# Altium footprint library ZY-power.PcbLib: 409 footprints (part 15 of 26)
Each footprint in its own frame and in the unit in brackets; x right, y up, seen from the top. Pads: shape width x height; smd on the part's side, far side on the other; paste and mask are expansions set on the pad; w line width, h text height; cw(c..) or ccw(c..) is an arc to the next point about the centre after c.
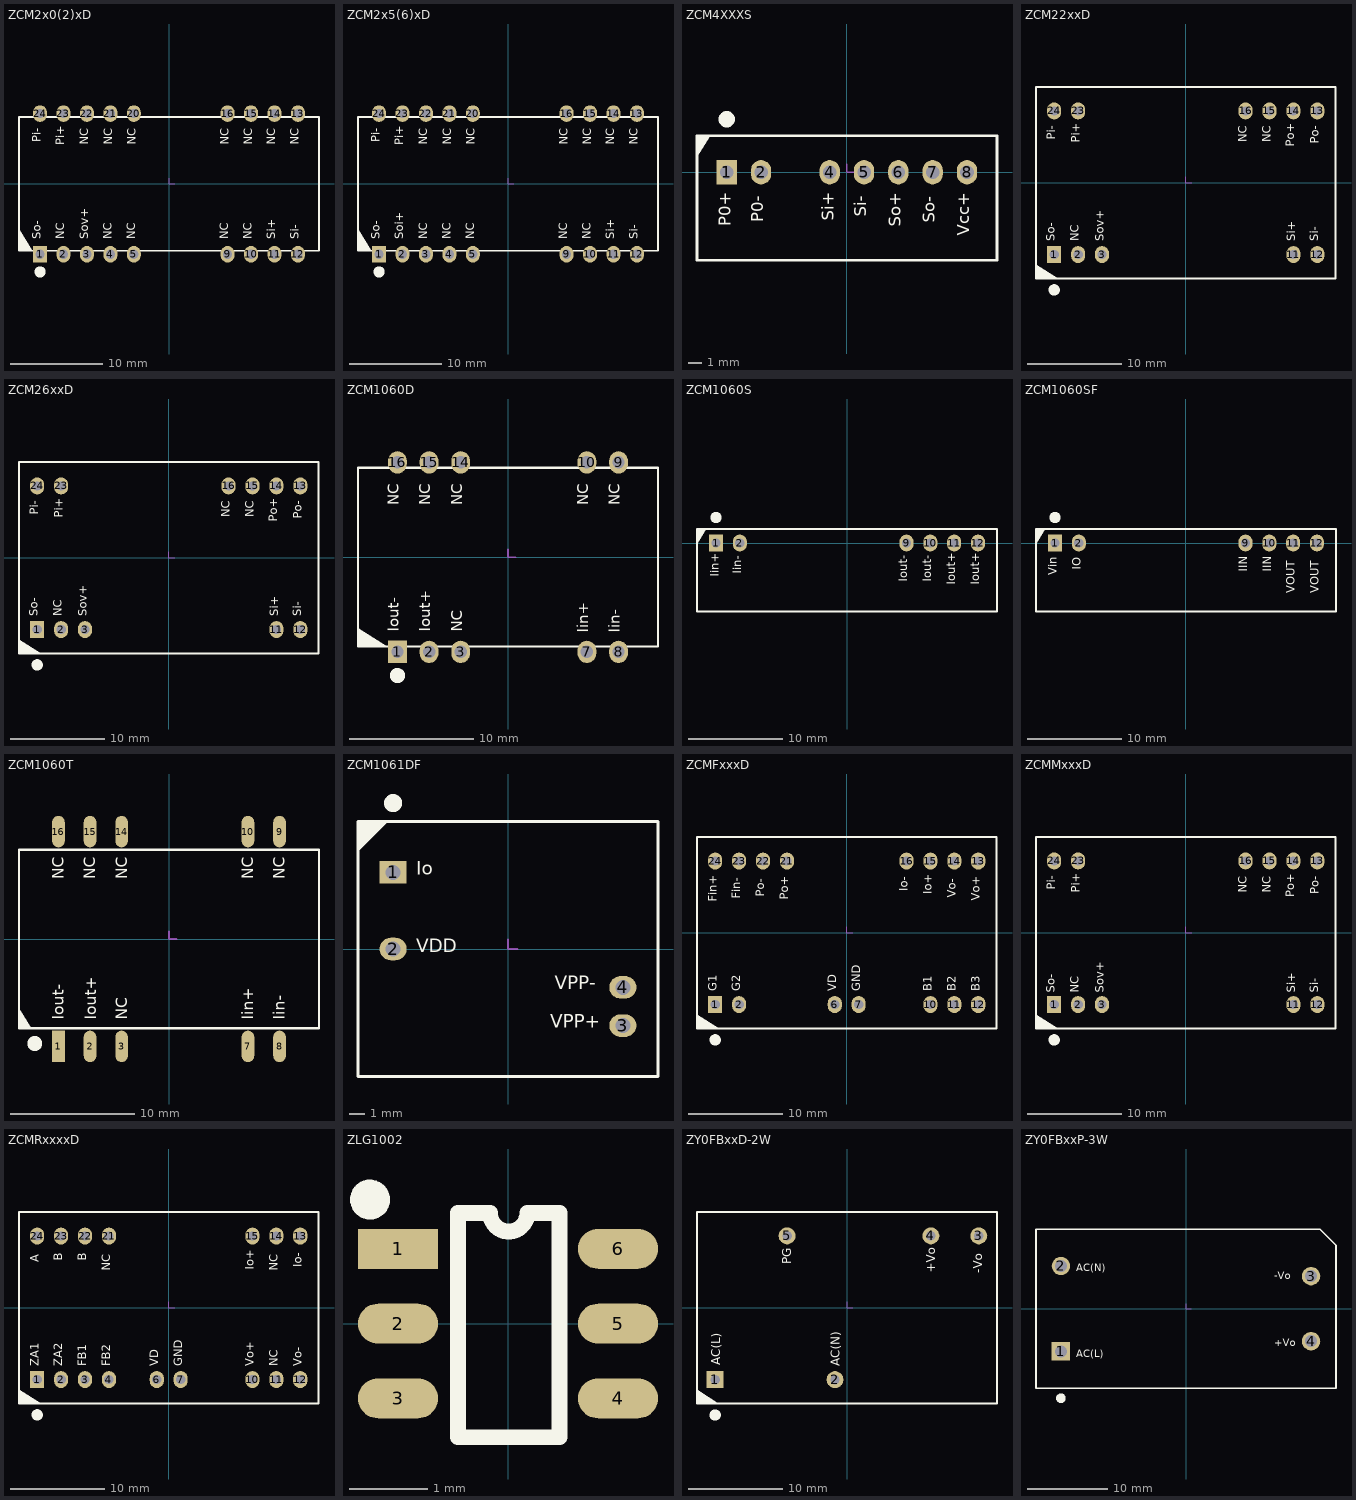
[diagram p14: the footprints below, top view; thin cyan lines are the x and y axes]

## ZCM2x0(2)xD [mm]
height 8.5
pads (18):
  rect 1.5x1.8 hole 1: 1(-13.97,-7.62)
  oval 1.5x1.8 hole 1: 2(-11.43,-7.62) 3(-8.89,-7.62) 4(-6.35,-7.62) 5(-3.81,-7.62) 9(6.35,-7.62) 10(8.89,-7.62) 11(11.43,-7.62) 12(13.97,-7.62) 13(13.97,7.62) 14(11.43,7.62) 15(8.89,7.62) 16(6.35,7.62) 20(-3.81,7.62) 21(-6.35,7.62) 22(-8.89,7.62) 23(-11.43,7.62) 24(-13.97,7.62)
Top Overlay:
  circle w1: c-13.97,-9.525 r0.1
  region: -16.25,-4.92 -16.25,-7.25 -14.79,-7.25
  lines w0.2: -16.25,-7.25 -16.25,7.25 16.25,7.25 16.25,-7.25 -16.25,-7.25
  text "Pi-" at -13.564,4.509 h1.52
  text "Pi+" at -11.024,4.2 h1.52
  text "NC" at 11.836,4.216 h1.52
  text "NC" at 14.376,4.216 h1.52
  text "Si-" at 14.376,-6.02 h1.52
  text "NC" at 6.756,-6.02 h1.52
  text "NC" at 9.296,-6.02 h1.52
  text "NC" at -5.867,-6.02 h1.52
  text "NC" at -3.327,-6.02 h1.52
  text "Sov+" at -8.433,-6.02 h1.52
  text "NC" at 9.347,4.216 h1.52
  text "NC" at 6.807,4.216 h1.52
  text "NC" at -8.433,4.216 h1.52
  text "NC" at -3.277,4.216 h1.52
  text "So-" at -13.564,-6.02 h1.52
  text "NC" at -5.842,4.216 h1.52
  text "NC" at -11.024,-6.02 h1.52
  text "Si+" at 11.836,-6.02 h1.52
Mechanical 15:
  lines w0.127: 0,0.635 0,0 0.635,0

## ZCM2x5(6)xD [mm]
height 8.5
pads (18):
  rect 1.5x1.8 hole 1: 1(-13.97,-7.62)
  oval 1.5x1.8 hole 1: 2(-11.43,-7.62) 3(-8.89,-7.62) 4(-6.35,-7.62) 5(-3.81,-7.62) 9(6.35,-7.62) 10(8.89,-7.62) 11(11.43,-7.62) 12(13.97,-7.62) 13(13.97,7.62) 14(11.43,7.62) 15(8.89,7.62) 16(6.35,7.62) 20(-3.81,7.62) 21(-6.35,7.62) 22(-8.89,7.62) 23(-11.43,7.62) 24(-13.97,7.62)
Top Overlay:
  circle w1: c-13.97,-9.525 r0.1
  region: -16.25,-4.92 -16.25,-7.25 -14.79,-7.25
  lines w0.2: -16.25,-7.25 -16.25,7.25 16.25,7.25 16.25,-7.25 -16.25,-7.25
  text "Pi-" at -13.564,4.509 h1.52
  text "Pi+" at -11.024,4.2 h1.52
  text "NC" at 11.836,4.216 h1.52
  text "NC" at 14.376,4.216 h1.52
  text "Si-" at 14.376,-6.02 h1.52
  text "NC" at 6.756,-6.02 h1.52
  text "NC" at 9.296,-6.02 h1.52
  text "NC" at -5.867,-6.02 h1.52
  text "NC" at -3.327,-6.02 h1.52
  text "NC" at -8.433,-6.02 h1.52
  text "NC" at 9.347,4.216 h1.52
  text "NC" at 6.807,4.216 h1.52
  text "NC" at -8.433,4.216 h1.52
  text "NC" at -3.277,4.216 h1.52
  text "So-" at -13.564,-6.02 h1.52
  text "NC" at -5.842,4.216 h1.52
  text "Soi+" at -11.024,-6.02 h1.52
  text "Si+" at 11.836,-6.02 h1.52
Mechanical 15:
  lines w0.127: 0,0.635 0,0 0.635,0

## ZCM4XXXS [mm]
pads (7):
  rect 1.5x1.8 hole 1: 1(-8.89,0)
  oval 1.5x1.8 hole 1: 2(-6.35,0) 4(-1.27,0) 5(1.27,0) 6(3.81,0) 7(6.35,0) 8(8.89,0)
Top Overlay:
  circle w1: c-8.89,3.925 r0.1
  region: -11.09,1.114 -11.09,2.7 -10.096,2.7
  lines w0.2: -11.09,-6.5 11.11,-6.5 11.11,2.7 -11.09,2.7 -11.09,-6.5
  text "Vcc+" at 9.357,-4.699 h1.52
  text "So-" at 6.817,-3.727 h1.52
  text "So+" at 4.277,-4.036 h1.52
  text "Si-" at 1.737,-3.273 h1.52
  text "Si+" at -0.676,-3.582 h1.52
  text "P0-" at -5.883,-3.684 h1.52
  text "P0+" at -8.296,-3.993 h1.52
Mechanical 15:
  lines w0.127: 0,0.635 0,0 0.635,0

## ZCM22xxD [mm]
height 9.5
pads (11):
  rect 1.5x1.8 hole 1: 1(-13.97,-7.62)
  oval 1.5x1.8 hole 1: 2(-11.43,-7.62) 3(-8.89,-7.62) 11(11.43,-7.62) 12(13.97,-7.62) 13(13.97,7.62) 14(11.43,7.62) 15(8.89,7.62) 16(6.35,7.62) 23(-11.43,7.62) 24(-13.97,7.62)
Top Overlay:
  circle w1: c-13.97,-11.375 r0.1
  region: -13.57,-10.15 -15.9,-10.15 -15.9,-8.69
  lines w0.2: -15.9,-10.15 -15.9,10.15 15.9,10.15 15.9,-10.15 -15.9,-10.15
  text "NC" at 6.782,4.281 h1.52
  text "NC" at 9.322,4.281 h1.52
  text "Po-" at 14.427,4.119 h1.52
  text "Si-" at 14.402,-6.223 h1.52
  text "So-" at -13.589,-6.223 h1.52
  text "Si+" at 11.938,-6.223 h1.52
  text "NC" at -11.049,-6.223 h1.52
  text "Sov+" at -8.382,-6.223 h1.52
  text "Pi-" at -13.513,4.574 h1.52
  text "Pi+" at -10.922,4.265 h1.52
  text "Po+" at 11.836,3.81 h1.52
Mechanical 15:
  lines w0.127: 0,0.635 0,0 0.635,0

## ZCM26xxD [mm]
height 9.5
pads (11):
  rect 1.5x1.8 hole 1: 1(-13.97,-7.62)
  oval 1.5x1.8 hole 1: 2(-11.43,-7.62) 3(-8.89,-7.62) 11(11.43,-7.62) 12(13.97,-7.62) 13(13.97,7.62) 14(11.43,7.62) 15(8.89,7.62) 16(6.35,7.62) 23(-11.43,7.62) 24(-13.97,7.62)
Top Overlay:
  circle w1: c-13.97,-11.375 r0.1
  region: -13.57,-10.15 -15.9,-10.15 -15.9,-8.69
  lines w0.2: -15.9,-10.15 15.9,-10.15 15.9,10.15 -15.9,10.15 -15.9,-10.15
  text "Po+" at 11.836,3.81 h1.52
  text "Pi+" at -10.922,4.265 h1.52
  text "Pi-" at -13.513,4.574 h1.52
  text "Po-" at 14.427,4.119 h1.52
  text "NC" at 9.322,4.281 h1.52
  text "NC" at 6.782,4.281 h1.52
  text "Sov+" at -8.382,-6.223 h1.52
  text "NC" at -11.049,-6.223 h1.52
  text "Si+" at 11.938,-6.223 h1.52
  text "So-" at -13.589,-6.223 h1.52
  text "Si-" at 14.402,-6.223 h1.52
Mechanical 15:
  lines w0.127: 0,0.635 0,0 0.635,0

## ZCM1060D [mm]
height 10
pads (10):
  rect 1.5x1.8 hole 1: 1(-8.89,-7.62)
  oval 1.5x1.8 hole 1: 2(-6.35,-7.62) 3(-3.81,-7.62) 7(6.35,-7.62) 8(8.89,-7.62) 9(8.89,7.62) 10(6.35,7.62) 14(-3.81,7.62) 15(-6.35,7.62) 16(-8.89,7.62)
Top Overlay:
  circle w1: c-8.89,-9.525 r0.1
  region: -9.735,-7.188 -12.065,-7.188 -12.065,-5.728
  lines w0.2: -12.065,-7.188 12.065,-7.188 12.065,7.188 -12.065,7.188 -12.065,-7.188
  text "Iin+" at 6.782,-6.071 h1.52
  text "Iin-" at 9.322,-6.071 h1.52
  text "Iout+" at -5.944,-5.994 h1.52
  text "NC" at -5.918,4.191 h1.52
  text "Iout-" at -8.484,-5.994 h1.52
  text "NC" at -8.458,4.191 h1.52
  text "NC" at -3.378,4.191 h1.52
  text "NC" at 6.782,4.191 h1.52
  text "NC" at 9.322,4.191 h1.52
  text "NC" at -3.353,-6.02 h1.52
Mechanical 15:
  lines w0.127: 0,0.635 0,0 0.635,0

## ZCM1060S [mm]
height 14.8
pads (6):
  rect 1.5x1.8 hole 1: 1(-13.97,0)
  oval 1.5x1.8 hole 1: 2(-11.43,0) 9(6.35,0) 10(8.89,0) 11(11.43,0) 12(13.97,0)
Top Overlay:
  circle w1: c-13.97,2.725 r0.1
  region: -16,-0.086 -16,1.5 -15.006,1.5
  lines w0.2: -16,-7.3 16,-7.3 16,1.5 -16,1.5 -16,-7.3
  text "Iout+" at 14.402,-4.445 h1.52
  text "Iout+" at 11.846,-4.445 h1.52
  text "Iout-" at 9.306,-4.136 h1.52
  text "Iout-" at 6.766,-4.136 h1.52
  text "Iin-" at -10.963,-3.302 h1.52
  text "Iin+" at -13.376,-3.611 h1.52

## ZCM1060SF [mm]
height 14.8
pads (6):
  rect 1.5x1.8 hole 1: 1(-13.97,0)
  oval 1.5x1.8 hole 1: 2(-11.43,0) 9(6.35,0) 10(8.89,0) 11(11.43,0) 12(13.97,0)
Top Overlay:
  circle w1: c-13.97,2.725 r0.1
  region: -16,-0.086 -16,1.5 -15.006,1.5
  lines w0.2: -16,-7.3 -16,1.5 16,1.5 16,-7.3 -16,-7.3
  text "Vin" at -13.46,-3.454 h1.52
  text "IO" at -10.92,-2.833 h1.52
  text "IIN" at 6.86,-3.086 h1.52
  text "IIN" at 9.4,-3.086 h1.52
  text "VOUT" at 11.94,-5.334 h1.52
  text "VOUT" at 14.48,-5.334 h1.52

## ZCM1060T [mil]
height 393.7
pads (10):
  rect 40x100 smd: 1(-350,-340)
  oval 40x100 smd: 2(-250,-340) 3(-150,-340) 7(250,-340) 8(350,-340) 9(350,340) 10(250,340) 14(-150,340) 15(-250,340) 16(-350,340)
Top Overlay:
  circle w39.37: c-425,-331.23 r3.94
  region: -475,-220.58 -475,-283 -435.88,-283
  lines w7.87: -475,-283 475,-283 475,283 -475,283 -475,-283
  text "Iin+" at 267,-255 h36
  text "Iin-" at 367,-255 h36
  text "Iout+" at -230,-255 h36
  text "NC" at -233,190 h36
  text "Iout-" at -334,-255 h36
  text "NC" at -333,190 h36
  text "NC" at -133,190 h36
  text "NC" at 267,190 h36
  text "NC" at 367,190 h36
  text "NC" at -132,-255 h36
Mechanical 15:
  lines w5: 0,25 0,0 25,0

## ZCM1061DF [mm]
height 7.05
pads (4):
  rect 1.8x1.5 hole 1: 1(-7.62,5.08)
  oval 1.8x1.5 hole 1: 2(-7.62,0) 3(7.62,-5.08) 4(7.62,-2.54)
Top Overlay:
  circle w1: c-7.62,9.677 r0.1
  region: -9.95,8.453 -7.975,8.452 -9.95,6.478
  lines w0.2: -9.95,-8.447 9.95,-8.447 9.95,8.453 -9.95,8.453 -9.95,-8.447
  text "VDD" at -6.096,-0.508 h1.52
  text "Io" at -6.097,4.643 h1.52
  text "VPP-" at 3.103,-2.966 h1.52
  text "VPP+" at 2.794,-5.532 h1.52
Mechanical 15:
  lines w0.127: 0,0.635 0,0 0.635,0

## ZCMFxxxD [mm]
pads (15):
  rect 1.5x1.8 hole 1: 1(-13.97,-7.62)
  oval 1.5x1.8 hole 1: 2(-11.43,-7.62) 6(-1.27,-7.62) 7(1.27,-7.62) 10(8.89,-7.62) 11(11.43,-7.62) 12(13.97,-7.62) 13(13.97,7.62) 14(11.43,7.62) 15(8.89,7.62) 16(6.35,7.62) 21(-6.35,7.62) 22(-8.89,7.62) 23(-11.43,7.62) 24(-13.97,7.62)
Top Overlay:
  circle w1: c-13.97,-11.375 r0.1
  region: -13.57,-10.15 -15.9,-10.15 -15.9,-8.69
  lines w0.2: -15.9,-10.15 -15.9,10.15 15.9,10.15 15.9,-10.15 -15.9,-10.15
  text "B3" at 14.437,-6.224 h1.52
  text "B2" at 11.897,-6.224 h1.52
  text "B1" at 9.357,-6.224 h1.52
  text "GND" at 1.737,-6.224 h1.52
  text "VD" at -0.803,-6.223 h1.52
  text "G2" at -10.963,-6.224 h1.52
  text "G1" at -13.503,-6.224 h1.52
  text "Vo+" at 14.437,3.422 h1.52
  text "Vo-" at 11.897,3.731 h1.52
  text "Io+" at 9.357,4.075 h1.52
  text "Io-" at 6.817,4.384 h1.52
  text "Po+" at -5.883,3.522 h1.52
  text "Po-" at -8.423,3.831 h1.52
  text "Fin-" at -10.963,3.611 h1.52
  text "Fin+" at -13.503,3.302 h1.52
Mechanical 15:
  lines w0.127: 0,0.635 0,0 0.635,0

## ZCMMxxxD [mm]
height 9.5
pads (11):
  rect 1.5x1.8 hole 1: 1(-13.97,-7.62)
  oval 1.5x1.8 hole 1: 2(-11.43,-7.62) 3(-8.89,-7.62) 11(11.43,-7.62) 12(13.97,-7.62) 13(13.97,7.62) 14(11.43,7.62) 15(8.89,7.62) 16(6.35,7.62) 23(-11.43,7.62) 24(-13.97,7.62)
Top Overlay:
  circle w1: c-13.97,-11.375 r0.1
  region: -13.57,-10.15 -15.9,-10.15 -15.9,-8.69
  lines w0.2: -15.9,-10.15 15.9,-10.15 15.9,10.15 -15.9,10.15 -15.9,-10.15
  text "Po+" at 11.836,3.787 h1.52
  text "Pi+" at -10.922,4.242 h1.52
  text "Pi-" at -13.513,4.551 h1.52
  text "Sov+" at -8.382,-6.375 h1.52
  text "NC" at -11.049,-6.375 h1.52
  text "Si+" at 11.938,-6.375 h1.52
  text "So-" at -13.589,-6.375 h1.52
  text "Si-" at 14.402,-6.375 h1.52
  text "Po-" at 14.427,4.096 h1.52
  text "NC" at 9.322,4.258 h1.52
  text "NC" at 6.782,4.258 h1.52
Mechanical 15:
  lines w0.127: 0,0.635 0,0 0.635,0

## ZCMRxxxxD [mm]
pads (16):
  rect 1.5x1.8 hole 1: 1(-13.97,-7.62)
  oval 1.5x1.8 hole 1: 2(-11.43,-7.62) 3(-8.89,-7.62) 4(-6.35,-7.62) 6(-1.27,-7.62) 7(1.27,-7.62) 10(8.89,-7.62) 11(11.43,-7.62) 12(13.97,-7.62) 13(13.97,7.62) 14(11.43,7.62) 15(8.89,7.62) 21(-6.35,7.62) 22(-8.89,7.62) 23(-11.43,7.62) 24(-13.97,7.62)
Top Overlay:
  circle w1: c-13.97,-11.375 r0.1
  region: -13.57,-10.15 -15.9,-10.15 -15.9,-8.69
  lines w0.2: -15.9,-10.15 15.9,-10.15 15.9,10.15 -15.9,10.15 -15.9,-10.15
  text "FB1" at -8.423,-6.223 h1.52
  text "FB2" at -5.883,-6.223 h1.52
  text "Vo-" at 14.437,-6.223 h1.52
  text "NC" at 11.897,-6.223 h1.52
  text "Vo+" at 9.357,-6.223 h1.52
  text "GND" at 1.737,-6.223 h1.52
  text "VD" at -0.803,-6.223 h1.52
  text "ZA2" at -10.963,-6.223 h1.52
  text "ZA1" at -13.503,-6.223 h1.52
  text "Io-" at 14.437,4.328 h1.52
  text "NC" at 11.897,3.937 h1.52
  text "Io+" at 9.357,4.019 h1.52
  text "NC" at -5.883,3.937 h1.52
  text "B" at -8.423,5.01 h1.52
  text "B" at -10.963,5.01 h1.52
  text "A" at -13.503,4.836 h1.52
Mechanical 15:
  lines w0.127: 0,0.635 0,0 0.635,0

## ZLG1002 [mil] "ZLG1002"
height 45.28
pads (6):
  rect 40x20 smd: 1(-55,37.4)
  oval 40x20 smd: 2(-55,0) 3(-55,-37.4) 4(55,-37.4) 5(55,0) 6(55,37.4)
Top Overlay:
  circle w10: c-69,62 r5
  lines w7.87: -25,55.4 -25,-56.8 25.7,-56.8 25.7,55.4 ; -9,55.4 ccw(c0.35,55.4) 9.7,55.4
  lines w8: -25,55.4 -9,55.4 ; 9.7,55.4 25.7,55.4
3D body "User Library-SOT-23-6.STEP": height 42.61, standoff -0.39, extent -48.5,-55 47,55

## ZY0FBxxD-2W [mm]
height 10.5
pads (5):
  rect 1.8x1.8 hole 1: 1(-13.97,-7.62)
  round 1.8 hole 1: 2(-1.27,-7.62) 3(13.97,7.62) 4(8.89,7.62) 5(-6.35,7.62)
Top Overlay:
  circle w1: c-13.97,-11.375 r0.1
  region: -13.57,-10.15 -15.9,-10.15 -15.9,-8.69
  lines w0.2: -15.9,-10.15 15.9,-10.15 15.9,10.15 -15.9,10.15 -15.9,-10.15
  text "AC(L)" at -13.462,-6.071 h0.91
  text "+Vo" at 9.373,3.708 h0.91
  text "-Vo" at 14.351,3.683 h0.91
  text "AC(N)" at -0.787,-6.223 h0.91
  text "PG" at -5.893,4.597 h0.91
Mechanical 15:
  lines w0.127: 0,0.635 0,0 0.635,0

## ZY0FBxxP-3W [mm]
pads (4):
  rect 2.3x2.3 hole 1.5: 1(-15.621,-5.334)
  round 2.3 hole 1.5: 2(-15.621,5.334) 3(15.621,4.064) 4(15.621,-4.064)
Top Overlay:
  circle w1: c-15.621,-11.174 r0.1
  lines w0.2: -18.737,-9.949 -18.737,9.949 16.721,9.949 18.737,7.933 18.737,-9.949 -18.737,-9.949
  text "+Vo" at 11.049,-4.699 h0.91
  text "-Vo" at 11.049,3.683 h0.91
  text "AC(N)" at -13.716,4.699 h0.91
  text "AC(L)" at -13.716,-6.096 h0.91
Mechanical 15:
  lines w0.127: 0,0.635 0,0 0.635,0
